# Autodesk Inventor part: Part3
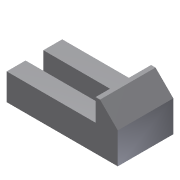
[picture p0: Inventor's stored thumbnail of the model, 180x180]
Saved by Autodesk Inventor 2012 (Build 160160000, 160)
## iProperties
Shininess: 77.0
Length Units: 11269
Angle Units: 11279
Time Units: 11290
Mass Units: 11283
Length Display Precision: 3
Angle Display Precision: 2
Created: 2002-01
Part Number: Part3
Document SubType Name: Modeling
Designer: ***
Density: 1 g/cm^3
Material: Default
Density: 0.0
Volumn: 0.0
Area: 0.0
PropertySet Name: Model Information
Control State: 0
Master: False
Checked Out: False
Author: ***
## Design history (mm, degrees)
sketch "Sketch2"
  geometry: L1 (23.289, -5.477)-(-16.711, -5.477); L2 (-16.711, -5.477)-(-16.711, 4.523); L3 (-16.711, 4.523)-(-18.711, 4.523); L4 (-18.711, 4.523)-(-26.711, -3.477); L5 (-26.711, -3.477)-(-26.711, -17.477); L6 (-26.711, -17.477)-(23.289, -17.477); L7 (23.289, -17.477)-(23.289, -5.477)
  constraints: 14 end point, 4 parallel, 1 horizontal, 1 perpendicular
  dimensions: "d0" = 50 distance of L5.end L6.end; "d1" = 12 distance of L6.end L1.start; "d2" = 22 distance between parallel lines of L3 L6; "d3" = 135 deg angle of L5 L4; "d4" = 2 distance of L2.end L3.end; "d5" = 40 distance of L1.start L1.end
extrude "Extrusion1" new body sketch "Sketch2" stored distance "d6" = 25; taper "d7" = 0 deg
sketch "Sketch3"
  geometry: L1 (-4, -8.5)-(36, -8.5); L2 (36, -8.5)-(36, -16.5); L3 (36, -16.5)-(-4, -16.5); L4 (-4, -16.5)-(-4, -8.5); L5 (40, -25)-(40, 0) reference; L6 (40, 0)-(0, 0) reference
  constraints: 8 end point, 2 parallel, 1 horizontal, 1 perpendicular
  dimensions: "d8" = 8 distance of L1.end L2.end; "d9" = 40 distance of L1.start L1.end; "d10" = 4 distance between parallel lines of L5 L2; "d11" = 8.5 distance between parallel lines of L6 L1
extrude "Extrusion2" cut sketch "Sketch3" stored distance "d12" = 25; taper "d13" = 0 deg
body "Solid1"
